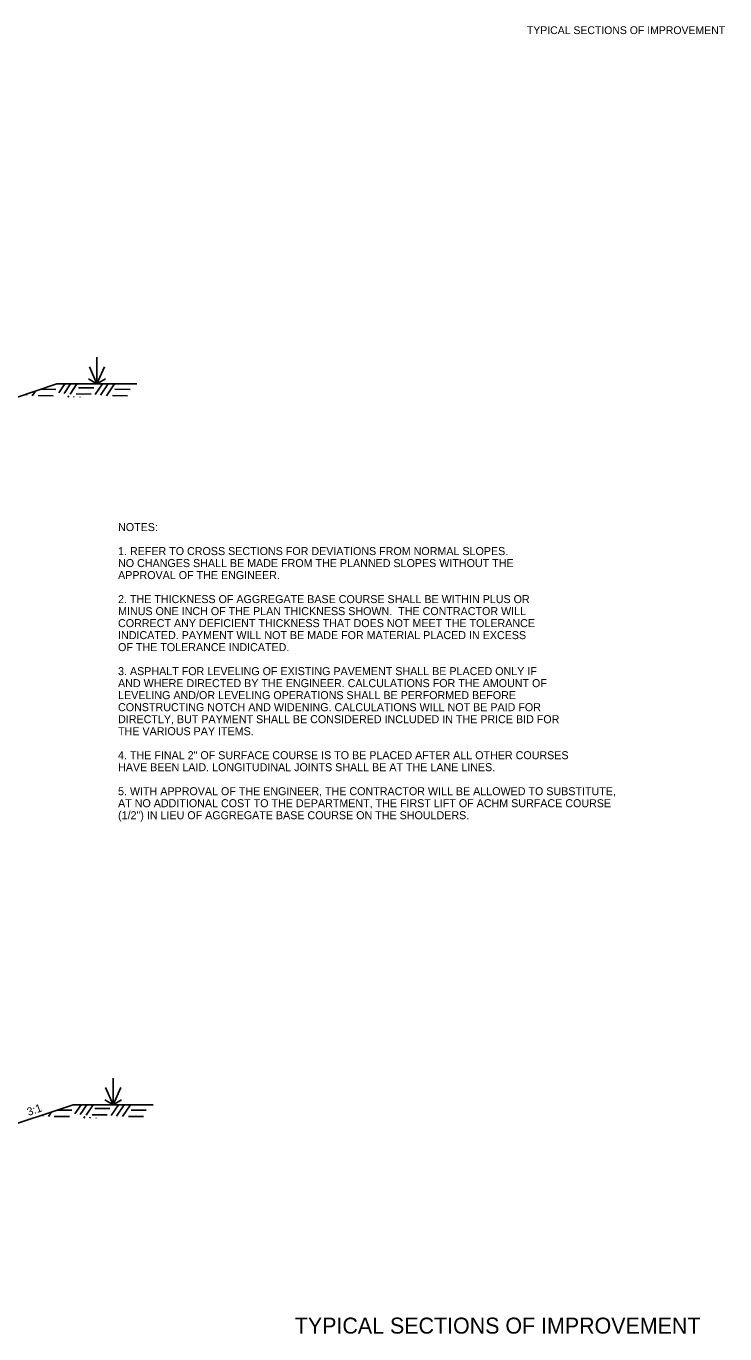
# Model space of a CAD drawing. Extents: x -900 to 15312, y 1857 to 2945.
# Drawn here: x 2476 to 3000, y 1965 to 2945 of the extents above; entities that cross this region are included whole.
import ezdxf

# ---------------------------------------------------------------- set-up
doc = ezdxf.new("R2010")
doc.units = 0
for name, color, linetype in [('R_Annotation', 7, 'Continuous'), ('R_Border', 7, 'Continuous'), ('R_Dimension', 7, 'Continuous'), ('R_Draft', 7, 'Continuous')]:
    doc.layers.add(name, color=color, linetype=linetype)

msp = doc.modelspace()

# ---------------------------------------------------------------- linework, layer by layer
at = {"layer": 'R_Annotation'}
for p, q in [((2439.09, 2656.72), (2499.09, 2676.72)), ((2499.09, 2676.72), (2559.09, 2676.72)), ((2451.18, 2116.41), (2511.18, 2136.41)), ((2511.18, 2136.41), (2571.18, 2136.41))]:
    msp.add_line(p, q, dxfattribs=at)
at = {"layer": 'R_Dimension'}
for p, q in [((2500.5, 2669.98), (2505.05, 2676.72)), ((2504.48, 2669.51), (2509.35, 2676.72)), ((2508.93, 2669.05), (2514.11, 2676.72)), ((2527.75, 2668.77), (2533.12, 2676.72)), ((2531.74, 2668.31), (2537.42, 2676.72)), ((2536.19, 2667.84), (2542.18, 2676.72)), ((2476.12, 2668.31), (2476.78, 2669.29)), ((2480.57, 2667.84), (2482.93, 2671.34)), ((2485.02, 2668.03), (2496.33, 2667.94)), ((2487.18, 2672.76), (2498.27, 2672.67)), ((2507.25, 2666.72), (2508.01, 2667.84)), ((2511.55, 2666.72), (2511.99, 2667.38)), ((2513.38, 2669.23), (2524.69, 2669.14)), ((2515.33, 2673.96), (2526.64, 2673.87)), ((2516.31, 2666.72), (2516.44, 2666.92)), ((2540.64, 2668.03), (2551.95, 2667.94)), ((2542.58, 2672.76), (2553.89, 2672.67)), ((2488.21, 2127.99), (2488.87, 2128.98)), ((2492.66, 2127.53), (2495.02, 2131.02)), ((2497.11, 2127.71), (2508.42, 2127.62)), ((2499.27, 2132.44), (2510.37, 2132.35)), ((2512.59, 2129.66), (2517.14, 2136.41)), ((2516.58, 2129.2), (2521.44, 2136.41)), ((2519.35, 2126.41), (2520.1, 2127.53)), ((2521.03, 2128.73), (2526.21, 2136.41)), ((2525.48, 2128.92), (2536.79, 2128.83)), ((2527.42, 2133.65), (2538.73, 2133.56)), ((2539.85, 2128.46), (2545.21, 2136.41)), ((2543.83, 2127.99), (2549.51, 2136.41)), ((2548.28, 2127.53), (2554.27, 2136.41)), ((2552.73, 2127.71), (2564.04, 2127.62)), ((2554.68, 2132.44), (2565.99, 2132.35)), ((2523.65, 2126.41), (2524.09, 2127.07)), ((2528.41, 2126.41), (2528.54, 2126.6))]:
    msp.add_line(p, q, dxfattribs=at)
at = {"layer": 'R_Draft'}
for p, q in [((2529.09, 2676.72), (2529.09, 2696.81)), ((2529.09, 2676.72), (2523.39, 2689.65)), ((2529.09, 2676.72), (2534.78, 2689.65)), ((2529.09, 2676.72), (2522.79, 2680.51)), ((2529.09, 2676.72), (2535.38, 2680.51)), ((2541.18, 2136.41), (2541.18, 2156.5)), ((2541.18, 2136.41), (2535.49, 2149.34)), ((2541.18, 2136.41), (2546.87, 2149.34)), ((2541.18, 2136.41), (2534.89, 2140.2)), ((2541.18, 2136.41), (2547.47, 2140.2))]:
    msp.add_line(p, q, dxfattribs=at)

# ---------------------------------------------------------------- texts
at = {"layer": 'R_Annotation'}
for s, height, p in [('NOTES:', 6, (2544.9, 2566.47)), ('1. REFER TO CROSS SECTIONS FOR DEVIATIONS FROM NORMAL SLOPES. ', 6, (2544.9, 2548.47)), ('NO CHANGES SHALL BE MADE FROM THE PLANNED SLOPES WITHOUT THE', 6, (2544.9, 2539.47)), ('APPROVAL OF THE ENGINEER.', 6, (2544.9, 2530.47)), ('2. THE THICKNESS OF AGGREGATE BASE COURSE SHALL BE WITHIN PLUS OR', 6, (2544.9, 2512.47)), ('MINUS ONE INCH OF THE PLAN THICKNESS SHOWN.  THE CONTRACTOR WILL', 6, (2544.9, 2503.47)), ('CORRECT ANY DEFICIENT THICKNESS THAT DOES NOT MEET THE TOLERANCE', 6, (2544.9, 2494.47)), ('INDICATED. PAYMENT WILL NOT BE MADE FOR MATERIAL PLACED IN EXCESS', 6, (2544.9, 2485.47)), ('OF THE TOLERANCE INDICATED.', 6, (2544.9, 2476.47)), ('3. ASPHALT FOR LEVELING OF EXISTING PAVEMENT SHALL BE PLACED ONLY IF', 6, (2544.9, 2458.47)), ('AND WHERE DIRECTED BY THE ENGINEER. CALCULATIONS FOR THE AMOUNT OF ', 6, (2544.9, 2449.47)), ('LEVELING AND/OR LEVELING OPERATIONS SHALL BE PERFORMED BEFORE', 6, (2544.9, 2440.47)), ('CONSTRUCTING NOTCH AND WIDENING. CALCULATIONS WILL NOT BE PAID FOR', 6, (2544.9, 2431.47)), ('DIRECTLY, BUT PAYMENT SHALL BE CONSIDERED INCLUDED IN THE PRICE BID FOR', 6, (2544.9, 2422.47)), ('THE VARIOUS PAY ITEMS.', 6, (2544.9, 2413.47)), ('4. THE FINAL 2" OF SURFACE COURSE IS TO BE PLACED AFTER ALL OTHER COURSES', 6, (2544.9, 2395.47)), ('HAVE BEEN LAID. LONGITUDINAL JOINTS SHALL BE AT THE LANE LINES.', 6, (2544.9, 2386.47)), ('5. WITH APPROVAL OF THE ENGINEER, THE CONTRACTOR WILL BE ALLOWED TO SUBSTITUTE,', 6, (2544.9, 2368.47)), ('AT NO ADDITIONAL COST TO THE DEPARTMENT, THE FIRST LIFT OF ACHM SURFACE COURSE', 6, (2544.9, 2359.47)), ('(1/2") IN LIEU OF AGGREGATE BASE COURSE ON THE SHOULDERS.', 6, (2544.9, 2350.47)), ('TYPICAL SECTIONS OF IMPROVEMENT', 12, (2677.38, 1964.9))]:
    msp.add_text(s, height=height, dxfattribs=at).set_placement(p)
msp.add_text('3:1', height=6, rotation=19.33935, dxfattribs=at).set_placement((2477.84, 2128.01))
at = {"layer": 'R_Border'}
msp.add_text('TYPICAL SECTIONS OF IMPROVEMENT', height=5.862, dxfattribs=at).set_placement((2851.36, 2938.99))

doc.saveas('drawing.dxf')
